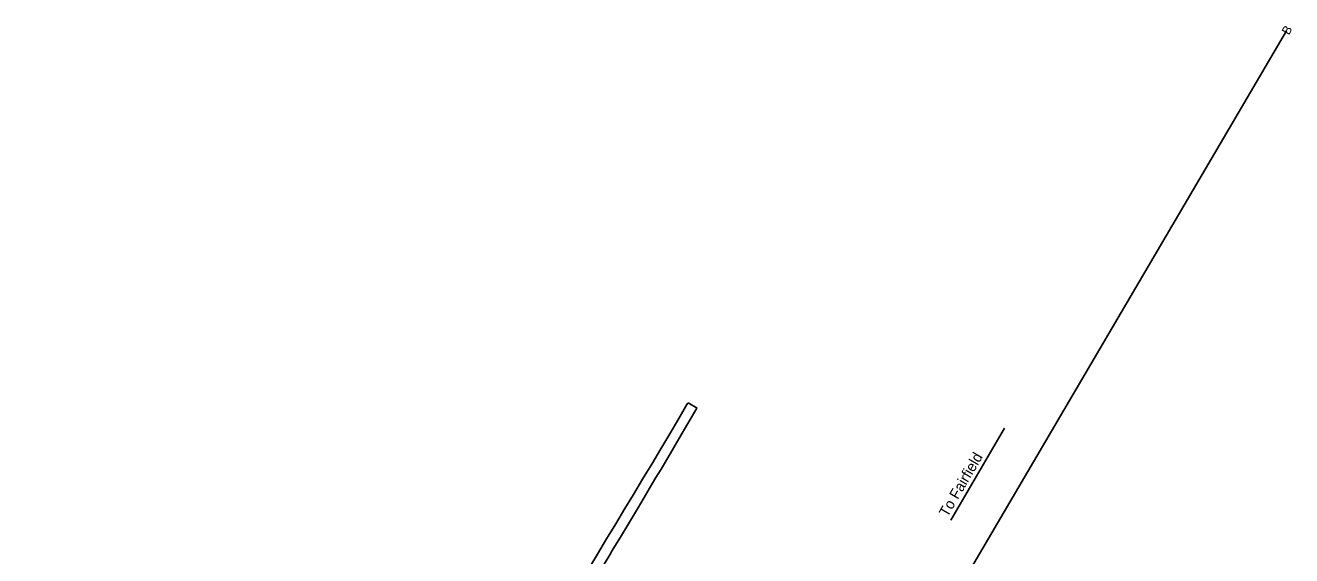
# Model space of a CAD drawing. Extents: x 1160458 to 1162290, y 615427 to 618737.
# Drawn here: x 1161573 to 1162290, y 618437 to 618737 of the extents above; entities that cross this region are included whole.
import ezdxf

# ---------------------------------------------------------------- set-up
doc = ezdxf.new("R2010")
doc.units = 0
for name, color, linetype in [('1', 7, 'Continuous'), ('D_Text_Standard', 7, 'Continuous'), ('Shoulder work for div plans (SB)', 7, 'Continuous')]:
    doc.layers.add(name, color=color, linetype=linetype)

msp = doc.modelspace()

# ---------------------------------------------------------------- linework, layer by layer
at = {"layer": '1'}
msp.add_line((1161209.81, 616899.51), (1162286.6, 618733.81), dxfattribs=at)
at = {"layer": 'D_Text_Standard'}
msp.add_line((1162096.75, 618457.02), (1162127.03, 618509.12), dxfattribs=at)
at = {"layer": 'Shoulder work for div plans (SB)'}
for p, q in [((1161947.51, 618522.45), (1161942.89, 618514.63)), ((1161948.07, 618511.8), (1161953.14, 618520.42)), ((1161953.2, 618520.52), (1161948.17, 618523.55)), ((1161953.14, 618520.42), (1161953.2, 618520.52)), ((1161942.89, 618514.63), (1161937.79, 618506.02)), ((1161937.79, 618506.02), (1161932.7, 618497.41)), ((1161932.7, 618497.41), (1161927.61, 618488.81)), ((1161932.86, 618485.95), (1161937.93, 618494.57)), ((1161927.61, 618488.81), (1161924.89, 618484.32)), ((1161917.26, 618471.7), (1161912.38, 618463.61)), ((1161924.59, 618472.18), (1161924.83, 618472.58)), ((1161912.38, 618463.61), (1161907.21, 618455.05)), ((1161907.21, 618455.05), (1161902.05, 618446.48)), ((1161910.46, 618448.46), (1161914.97, 618456)), ((1161905.29, 618439.91), (1161910.46, 618448.46)), ((1161902.05, 618446.48), (1161896.89, 618437.92))]:
    msp.add_line(p, q, dxfattribs=at)
for points in [[(1161937.93, 618494.57), (1161943, 618503.18), (1161948.07, 618511.8)], [(1161924.89, 618484.32), (1161922.43, 618480.25), (1161917.26, 618471.7)], [(1161924.83, 618472.58), (1161929.97, 618481.16), (1161932.86, 618485.95)], [(1161914.97, 618456), (1161919.48, 618463.58), (1161924.59, 618472.18)], [(1161898.6, 618428.91), (1161903.8, 618437.46), (1161905.29, 618439.91)], [(1161896.89, 618437.92), (1161891.73, 618429.35), (1161886.57, 618420.78)]]:
    msp.add_lwpolyline(points, dxfattribs=at)
msp.add_arc((1165538.1, 616366.76), 4188, 149.00311, 149.02067, dxfattribs=at)

# ---------------------------------------------------------------- texts
msp.add_text('B', height=5, rotation=59.58575).set_placement((1162287.93, 618731.14))
at = {"layer": 'D_Text_Standard'}
msp.add_text('To Fairfield', height=6, rotation=59.7924, dxfattribs=at).set_placement((1162094.88, 618458.41))

doc.saveas('drawing.dxf')
